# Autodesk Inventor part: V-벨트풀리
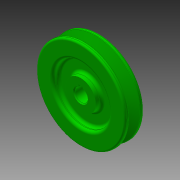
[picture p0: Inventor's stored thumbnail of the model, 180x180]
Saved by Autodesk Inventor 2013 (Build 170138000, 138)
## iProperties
Created: 2024-02
Part Number: V-벨트풀리
Material: 주철, 주조
Document SubType Name: Modeling
Designer: mdu-01
Density: 1 g/cm^3
Author: mdu-01
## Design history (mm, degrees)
sketch "스케치1"
  geometry: L1 (0, 10)-(0, -10); L2 (0, 0)-(35, 0); L3 (0, 10)-(16, 10); L4 (16, 10)-(16, 6); L5 (19, 3)-(27, 3); L6 (30, 6)-(30, 7); L7 (33, 10)-(45.5, 10); L8 (47.5, 8)-(47.5, 6.346); L9 (47.146, 5.868)-(35.708, 2.37); L10 (0, -10)-(16, -10); L11 (16, -10)-(16, -6); L12 (19, -3)-(27, -3); L13 (30, -6)-(30, -7); L14 (33, -10)-(45.5, -10); L15 (47.5, -8)-(47.5, -6.346); L16 (47.146, -5.868)-(35.708, -2.37); L17 (35, 1.414)-(35, -1.414); L18 (7, 9)-(7, -9); L19 (9.3, 10)-(9.3, -10); L20 (-7, 10)-(-7, -10); L21 (7, 9)-(8, 10); L22 (7, -9)-(8, -10); A1 r 0.5 centre (47, 6.346) between (47.146, 5.868) and (47.5, 6.346); A2 r 0.5 centre (47, -6.346) between (47.5, -6.346) and (47.146, -5.868); A3 r 1 centre (36, 1.414) between (35.708, 2.37) and (35, 1.414); A4 r 1 centre (36, -1.414) between (35, -1.414) and (35.708, -2.37); A5 r 2 centre (45.5, 8) between (47.5, 8) and (45.5, 10); A6 r 2 centre (45.5, -8) between (45.5, -10) and (47.5, -8); A7 r 3 centre (33, 7) between (33, 10) and (30, 7); A8 r 3 centre (27, 6) between (27, 3) and (30, 6); A9 r 3 centre (27, -6) between (30, -6) and (27, -3); A10 r 3 centre (33, -7) between (30, -7) and (33, -10); A11 r 3 centre (19, -6) between (19, -3) and (16, -6); A12 r 3 centre (19, 6) between (16, 6) and (19, 3); 18 further points
  constraints: 44 end point, 35 point on line, 24 point on circle, 24 tangent, 12 centre point, 10 symmetric about line, 8 equal radius, 6 parallel, 4 midpoint, 3 perpendicular, 2 collinear, 1 coincident, 1 vertical
  dimensions: "d0" = 20 distance of L1.start L1.end; "d2" = 86 diameter of point (43, 4.6) L1; "d3" = 9.2 diameter of point (43, 4.6) L2; "d4" = 34 deg angle of L16 L9; "d5" = 4.5 distance from line of L8 point (43, 4.6); "d6" = 8 distance from line of L17 point (43, 4.6); "d7" = 14 diameter of L18 L1; "d8" = 16.3 distance between parallel lines of L19 L20; "d9" = 32 diameter of L11 L1; "d10" = 60 diameter of L13 L1; "d11" = 6 distance between parallel lines of L12 L5; "d12" = 0.5 radius of A1; "d13" = 1 radius of A3; "d14" = 2 radius of A5; "d15" = 1 distance of L18.start point (7, 10); "d17" = 1 distance of L18.end point (7, -10) (= d15); "d19" = 45 deg angle of L22 L18; "d20" = 45 deg angle of L21 L18; "d21" = 3 radius of A7
revolve "회전1" stored, may be unused: angle "d22" = 90 deg
extrude "돌출1" cut sketch "스케치1" stored distance "d23" = 5; taper "d24" = 0 deg
node "솔리드1"
